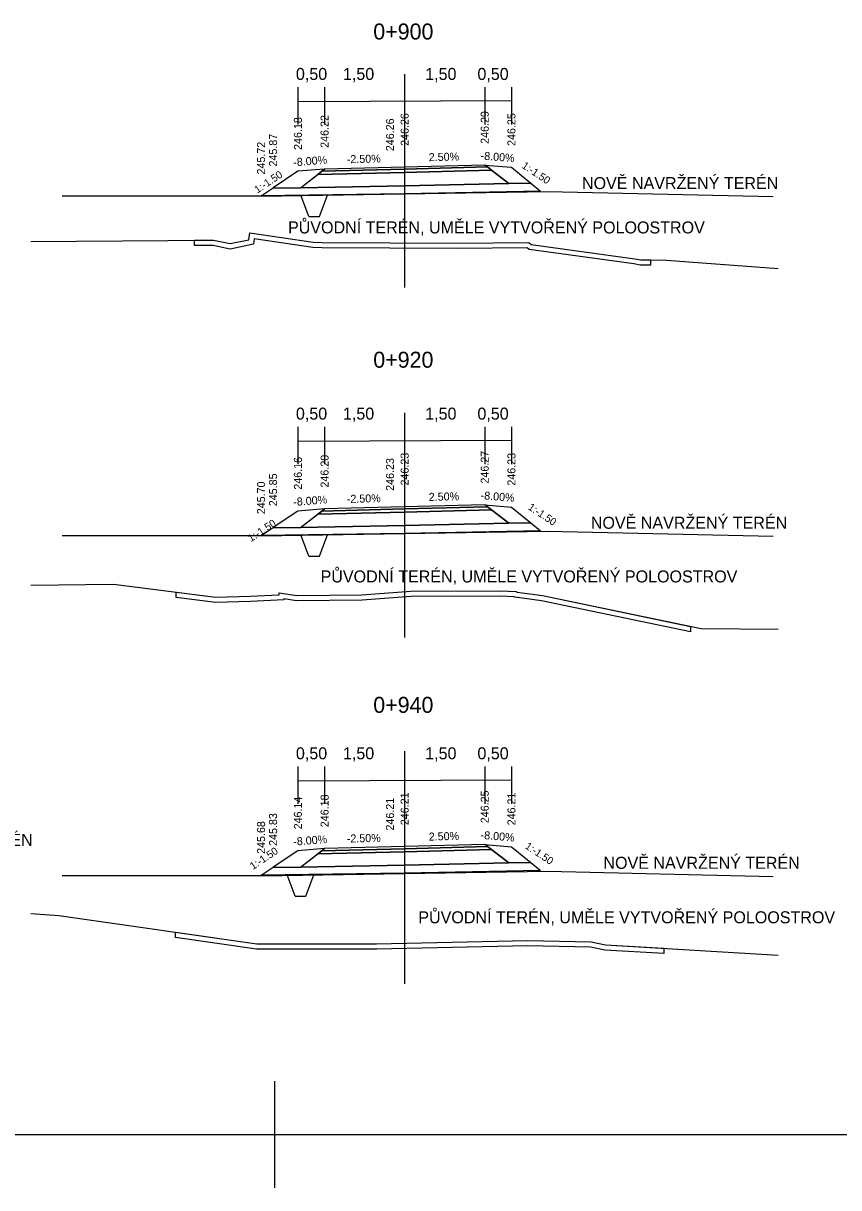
# Model space of a CAD drawing. Extents: x -552501 to -552394, y -1029983 to -1029892.
# Drawn here: x -552483.46 to -552468.19, y -1029983.45 to -1029961.62 of the extents above; entities that cross this region are included whole.
import ezdxf

# ---------------------------------------------------------------- set-up
doc = ezdxf.new("R2010")
doc.units = 0
for name, color, linetype in [('1', 7, 'Continuous'), ('16', 7, 'Continuous'), ('60', 7, 'Continuous'), ('9', 7, 'Continuous'), ('FORMATY', 7, 'Continuous'), ('Implicitní', 7, 'Continuous'), ('rámeček', 7, 'Continuous')]:
    doc.layers.add(name, color=color, linetype=linetype)

msp = doc.modelspace()

# ---------------------------------------------------------------- linework, layer by layer
for p, q in [((-552478.995, -1029964.866), (-552482.731, -1029964.866)), ((-552478.112, -1029965.248), (-552478.262, -1029964.848)), ((-552477.912, -1029965.248), (-552477.762, -1029964.848)), ((-552478.112, -1029965.248), (-552477.912, -1029965.248)), ((-552478.995, -1029971.233), (-552482.731, -1029971.233)), ((-552478.112, -1029971.615), (-552478.262, -1029971.215)), ((-552477.912, -1029971.615), (-552477.762, -1029971.215)), ((-552478.112, -1029971.615), (-552477.912, -1029971.615)), ((-552478.995, -1029977.607), (-552482.731, -1029977.607)), ((-552478.369, -1029977.983), (-552478.519, -1029977.583)), ((-552478.169, -1029977.983), (-552478.019, -1029977.583)), ((-552478.369, -1029977.983), (-552478.169, -1029977.983))]:
    msp.add_line(p, q)
for points in [[(-552477.816, -1029964.358), (-552478.316, -1029964.398), (-552478.781, -1029964.708), (-552478.266, -1029964.708)], [(-552478.266, -1029964.708), (-552477.944, -1029964.458), (-552476.316, -1029964.421), (-552474.688, -1029964.377), (-552474.366, -1029964.627), (-552476.316, -1029964.671)], [(-552476.316, -1029964.361), (-552477.867, -1029964.398), (-552477.944, -1029964.458), (-552476.316, -1029964.421), (-552474.688, -1029964.377), (-552474.765, -1029964.317), (-552476.316, -1029964.361), (-552474.765, -1029964.317), (-552474.816, -1029964.283), (-552476.316, -1029964.321), (-552477.816, -1029964.358), (-552477.867, -1029964.398)], [(-552477.944, -1029964.458), (-552477.867, -1029964.398), (-552476.316, -1029964.361), (-552474.765, -1029964.317), (-552474.688, -1029964.377), (-552476.316, -1029964.421)], [(-552474.816, -1029964.283), (-552474.316, -1029964.323), (-552473.955, -1029964.621), (-552474.366, -1029964.627), (-552474.688, -1029964.377), (-552474.765, -1029964.317)], [(-552479.006, -1029964.858), (-552478.781, -1029964.708), (-552478.266, -1029964.708), (-552476.316, -1029964.671), (-552474.366, -1029964.627), (-552473.955, -1029964.621), (-552473.77, -1029964.771), (-552476.316, -1029964.821)], [(-552480.255, -1029965.691), (-552479.896, -1029965.688), (-552479.585, -1029965.753), (-552479.236, -1029965.681), (-552479.218, -1029965.55), (-552478.027, -1029965.724), (-552477.86, -1029965.735), (-552475.325, -1029965.744), (-552473.988, -1029965.734), (-552473.944, -1029965.768), (-552472.007, -1029966.036), (-552471.894, -1029966.059), (-552471.71, -1029966.06), (-552471.71, -1029966.16), (-552471.905, -1029966.159), (-552472.024, -1029966.134), (-552473.984, -1029965.863), (-552474.021, -1029965.834), (-552475.325, -1029965.844), (-552477.864, -1029965.835), (-552478.038, -1029965.824), (-552479.133, -1029965.663), (-552479.147, -1029965.765), (-552479.585, -1029965.855), (-552479.906, -1029965.788), (-552480.255, -1029965.791)], [(-552477.816, -1029970.726), (-552478.316, -1029970.766), (-552478.781, -1029971.076), (-552478.266, -1029971.076)], [(-552478.266, -1029971.076), (-552477.944, -1029970.826), (-552476.316, -1029970.788), (-552474.688, -1029970.745), (-552474.366, -1029970.995), (-552476.316, -1029971.038)], [(-552476.316, -1029970.728), (-552477.867, -1029970.766), (-552477.944, -1029970.826), (-552476.316, -1029970.788), (-552474.688, -1029970.745), (-552474.765, -1029970.685), (-552476.316, -1029970.728), (-552474.765, -1029970.685), (-552474.816, -1029970.651), (-552476.316, -1029970.688), (-552477.816, -1029970.726), (-552477.867, -1029970.766)], [(-552477.944, -1029970.826), (-552477.867, -1029970.766), (-552476.316, -1029970.728), (-552474.765, -1029970.685), (-552474.688, -1029970.745), (-552476.316, -1029970.788)], [(-552474.816, -1029970.651), (-552474.316, -1029970.691), (-552473.955, -1029970.988), (-552474.366, -1029970.995), (-552474.688, -1029970.745), (-552474.765, -1029970.685)], [(-552479.006, -1029971.226), (-552478.781, -1029971.076), (-552478.266, -1029971.076), (-552476.316, -1029971.038), (-552474.366, -1029970.995), (-552473.955, -1029970.988), (-552473.77, -1029971.138), (-552476.316, -1029971.188)], [(-552480.596, -1029972.286), (-552479.853, -1029972.379), (-552479.21, -1029972.36), (-552478.669, -1029972.334), (-552478.664, -1029972.299), (-552478.337, -1029972.347), (-552477.116, -1029972.339), (-552476.2, -1029972.267), (-552474.516, -1029972.259), (-552474.226, -1029972.274), (-552474.21, -1029972.287), (-552473.736, -1029972.352), (-552470.959, -1029972.929), (-552470.959, -1029973.031), (-552473.753, -1029972.451), (-552474.25, -1029972.382), (-552474.262, -1029972.373), (-552474.518, -1029972.359), (-552476.196, -1029972.367), (-552477.112, -1029972.439), (-552478.344, -1029972.447), (-552478.579, -1029972.413), (-552478.582, -1029972.43), (-552479.206, -1029972.459), (-552479.858, -1029972.479), (-552480.596, -1029972.387)], [(-552477.816, -1029977.093), (-552478.316, -1029977.133), (-552478.781, -1029977.443), (-552478.266, -1029977.443)], [(-552476.316, -1029977.095), (-552477.867, -1029977.133), (-552477.944, -1029977.193), (-552476.316, -1029977.155), (-552474.688, -1029977.112), (-552474.765, -1029977.052), (-552476.316, -1029977.095), (-552474.765, -1029977.052), (-552474.816, -1029977.018), (-552476.316, -1029977.055), (-552477.816, -1029977.093), (-552477.867, -1029977.133)], [(-552477.944, -1029977.193), (-552477.867, -1029977.133), (-552476.316, -1029977.095), (-552474.765, -1029977.052), (-552474.688, -1029977.112), (-552476.316, -1029977.155)], [(-552474.816, -1029977.018), (-552474.316, -1029977.058), (-552473.955, -1029977.356), (-552474.366, -1029977.362), (-552474.688, -1029977.112), (-552474.765, -1029977.052)], [(-552478.266, -1029977.443), (-552477.944, -1029977.193), (-552476.316, -1029977.155), (-552474.688, -1029977.112), (-552474.366, -1029977.362), (-552476.316, -1029977.405)], [(-552479.006, -1029977.593), (-552478.781, -1029977.443), (-552478.266, -1029977.443), (-552476.316, -1029977.405), (-552474.366, -1029977.362), (-552473.955, -1029977.356), (-552473.77, -1029977.506), (-552476.316, -1029977.555)], [(-552480.607, -1029978.661), (-552479.087, -1029978.877), (-552478.6, -1029978.881), (-552476.841, -1029978.88), (-552474.014, -1029978.817), (-552472.825, -1029978.844), (-552472.551, -1029978.899), (-552471.458, -1029978.963), (-552471.458, -1029979.063), (-552472.564, -1029978.998), (-552472.836, -1029978.944), (-552474.014, -1029978.917), (-552476.84, -1029978.98), (-552478.6, -1029978.981), (-552479.094, -1029978.977), (-552480.607, -1029978.762)]]:
    msp.add_lwpolyline(points, close=True)
for points in [[(-552478.995, -1029964.866), (-552473.637, -1029964.776), (-552469.411, -1029964.873)], [(-552483.316, -1029965.713), (-552479.896, -1029965.688), (-552479.585, -1029965.753), (-552479.236, -1029965.681), (-552479.218, -1029965.55), (-552478.027, -1029965.724), (-552477.86, -1029965.735), (-552475.325, -1029965.744), (-552473.988, -1029965.734), (-552473.944, -1029965.768), (-552472.007, -1029966.036), (-552471.894, -1029966.059), (-552471.412, -1029966.062), (-552469.316, -1029966.218)], [(-552478.995, -1029971.233), (-552473.637, -1029971.143), (-552469.411, -1029971.24)], [(-552483.316, -1029972.155), (-552481.768, -1029972.139), (-552479.853, -1029972.379), (-552479.21, -1029972.36), (-552478.669, -1029972.334), (-552478.664, -1029972.299), (-552478.337, -1029972.347), (-552477.116, -1029972.339), (-552476.2, -1029972.267), (-552474.516, -1029972.259), (-552474.226, -1029972.274), (-552474.21, -1029972.287), (-552473.736, -1029972.352), (-552470.761, -1029972.97), (-552469.316, -1029972.979)], [(-552478.995, -1029977.607), (-552473.637, -1029977.517), (-552469.411, -1029977.614)], [(-552483.316, -1029978.311), (-552482.792, -1029978.35), (-552479.087, -1029978.877), (-552478.6, -1029978.881), (-552476.841, -1029978.88), (-552474.014, -1029978.817), (-552472.825, -1029978.844), (-552472.551, -1029978.899), (-552469.316, -1029979.09)]]:
    msp.add_lwpolyline(points)
at = {"layer": '60'}
for p, q in [((-552476.316, -1029962.577), (-552476.316, -1029966.575)), ((-552476.316, -1029968.923), (-552476.316, -1029973.136)), ((-552476.316, -1029975.269), (-552476.316, -1029979.626))]:
    msp.add_line(p, q, dxfattribs=at)
at = {"layer": '9'}
for p, q in [((-552478.316, -1029962.821), (-552478.316, -1029963.518)), ((-552477.816, -1029962.821), (-552477.816, -1029963.518)), ((-552476.316, -1029962.821), (-552476.316, -1029964.321)), ((-552474.816, -1029962.821), (-552474.816, -1029963.518)), ((-552474.316, -1029962.821), (-552474.316, -1029963.518)), ((-552478.316, -1029969.188), (-552478.316, -1029969.886)), ((-552477.816, -1029969.188), (-552477.816, -1029969.886)), ((-552476.316, -1029969.188), (-552476.316, -1029970.688)), ((-552474.816, -1029969.188), (-552474.816, -1029969.886)), ((-552474.316, -1029969.188), (-552474.316, -1029969.886)), ((-552478.316, -1029975.555), (-552478.316, -1029976.253)), ((-552477.816, -1029975.555), (-552477.816, -1029976.253)), ((-552476.316, -1029975.555), (-552476.316, -1029977.055)), ((-552474.816, -1029975.555), (-552474.816, -1029976.253)), ((-552474.316, -1029975.555), (-552474.316, -1029976.253))]:
    msp.add_line(p, q, dxfattribs=at)
at = {"layer": 'FORMATY'}
for p, q in [((-552478.755, -1029981.45), (-552478.755, -1029983.45)), ((-552479.755, -1029982.45), (-552477.755, -1029982.45))]:
    msp.add_line(p, q, dxfattribs=at)
at = {"layer": 'Implicitní'}
for p, q in [((-552478.306, -1029963.088), (-552474.316, -1029963.071)), ((-552478.306, -1029969.456), (-552474.316, -1029969.438)), ((-552478.306, -1029975.823), (-552474.316, -1029975.805))]:
    msp.add_line(p, q, dxfattribs=at)
at = {"layer": 'rámeček'}
for p, q in [((-552478.755, -1029981.95), (-552478.755, -1029982.45)), ((-552499.755, -1029982.45), (-552436.755, -1029982.45)), ((-552499.755, -1029982.45), (-552415.755, -1029982.45)), ((-552499.755, -1029982.45), (-552415.755, -1029982.45))]:
    msp.add_line(p, q, dxfattribs=at)

# ---------------------------------------------------------------- texts
for rotation, p in [(33.6902, (-552479.075, -1029964.817)), (326.3098, (-552474.133, -1029964.324)), (326.3098, (-552474.017, -1029970.725)), (33.6902, (-552479.196, -1029971.352)), (33.6902, (-552479.158, -1029977.496)), (326.3098, (-552474.073, -1029977.08))]:
    msp.add_text('1:-1.50', height=0.14, rotation=rotation).set_placement(p)
at = {"layer": '1'}
for s, p in [('0+900', (-552476.904, -1029961.928)), ('0+920', (-552476.904, -1029968.08)), ('0+940', (-552476.904, -1029974.549))]:
    msp.add_text(s, height=0.3, dxfattribs=at).set_placement(p)
at = {"layer": '16'}
for s, p in [('0,50', (-552478.353, -1029962.686)), ('1,50', (-552477.472, -1029962.686)), ('1,50', (-552475.931, -1029962.686)), ('0,50', (-552474.953, -1029962.686)), ('NOVĚ NAVRŽENÝ TERÉN', (-552472.994, -1029964.732)), ('PŮVODNÍ TERÉN, UMĚLE VYTVOŘENÝ POLOOSTROV', (-552478.501, -1029965.563)), ('0,50', (-552478.353, -1029969.053)), ('1,50', (-552477.472, -1029969.053)), ('1,50', (-552475.931, -1029969.053)), ('0,50', (-552474.953, -1029969.053)), ('NOVĚ NAVRŽENÝ TERÉN', (-552472.828, -1029971.099)), ('PŮVODNÍ TERÉN, UMĚLE VYTVOŘENÝ POLOOSTROV', (-552477.891, -1029972.105)), ('0,50', (-552478.353, -1029975.42)), ('1,50', (-552477.472, -1029975.42)), ('1,50', (-552475.931, -1029975.42)), ('0,50', (-552474.953, -1029975.42)), ('NOVĚ NAVRŽENÝ TERÉN', (-552486.963, -1029977.042)), ('NOVĚ NAVRŽENÝ TERÉN', (-552472.592, -1029977.473)), ('PŮVODNÍ TERÉN, UMĚLE VYTVOŘENÝ POLOOSTROV', (-552476.06, -1029978.494))]:
    msp.add_text(s, height=0.225, dxfattribs=at).set_placement(p)
for s, rotation, p in [('246.26', 90, (-552476.241, -1029963.921)), ('246.29', 90, (-552474.741, -1029963.883)), ('246.25', 90, (-552474.241, -1029963.923)), ('246.18', 90, (-552478.241, -1029963.998)), ('246.22', 90, (-552477.741, -1029963.958)), ('246.26', 90, (-552476.516, -1029964.021)), ('245.87', 90, (-552478.706, -1029964.308)), ('245.72', 90, (-552478.931, -1029964.458)), ('-8.00%', 4.5739, (-552478.397, -1029964.305)), ('-2.50%', 1.4321, (-552477.398, -1029964.248)), ('2.50%', 1.4321, (-552475.863, -1029964.209)), ('-8.00%', 355.4261, (-552474.897, -1029964.177)), ('246.27', 90, (-552474.741, -1029970.251)), ('246.16', 90, (-552478.241, -1029970.366)), ('246.20', 90, (-552477.741, -1029970.326)), ('246.23', 90, (-552476.516, -1029970.388)), ('246.23', 90, (-552476.241, -1029970.288)), ('246.23', 90, (-552474.241, -1029970.291)), ('245.85', 90, (-552478.706, -1029970.676)), ('245.70', 90, (-552478.931, -1029970.826)), ('-8.00%', 4.5739, (-552478.397, -1029970.672)), ('-2.50%', 1.4321, (-552477.398, -1029970.615)), ('2.50%', 1.4321, (-552475.863, -1029970.577)), ('-8.00%', 355.4261, (-552474.897, -1029970.544)), ('246.14', 90, (-552478.241, -1029976.733)), ('246.18', 90, (-552477.741, -1029976.693)), ('246.21', 90, (-552476.516, -1029976.755)), ('246.21', 90, (-552476.241, -1029976.655)), ('246.25', 90, (-552474.741, -1029976.618)), ('246.21', 90, (-552474.241, -1029976.658)), ('245.83', 90, (-552478.706, -1029977.043)), ('245.68', 90, (-552478.931, -1029977.193)), ('-8.00%', 4.5739, (-552478.397, -1029977.039)), ('-2.50%', 1.4321, (-552477.398, -1029976.982)), ('2.50%', 1.4321, (-552475.863, -1029976.944)), ('-8.00%', 355.4261, (-552474.897, -1029976.911))]:
    msp.add_text(s, height=0.15, rotation=rotation, dxfattribs=at).set_placement(p)

doc.saveas('drawing.dxf')
